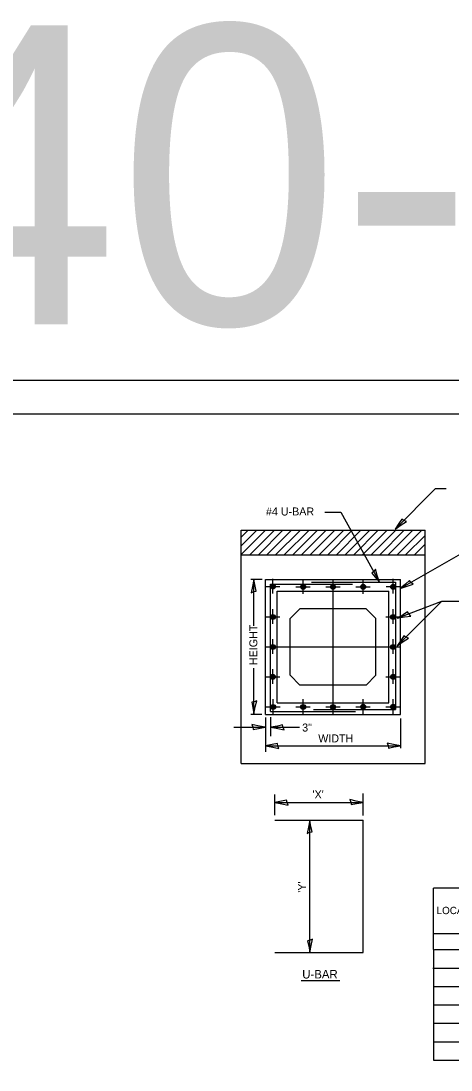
# Model space of a CAD drawing. Extents: x 2133490 to 2172050, y 2138301 to 2145980.
# Drawn here: x 2145603 to 2145925, y 2145157 to 2145944 of the extents above; entities that cross this region are included whole.
import ezdxf

# ---------------------------------------------------------------- set-up
doc = ezdxf.new("R2010")
doc.units = 0
for name, color, linetype in [('Level 23', 7, 'Continuous'), ('Level 40', 7, 'Continuous'), ('Level 63', 7, 'Continuous'), ('ROW_PR_Notes', 7, 'Continuous'), ('Sheets_50 Reference Boundary', 7, 'Continuous'), ('Sheets_General Details', 7, 'Continuous'), ('Sheets_Printer Plotting Border', 7, 'Continuous')]:
    doc.layers.add(name, color=color, linetype=linetype)

msp = doc.modelspace()

# ---------------------------------------------------------------- linework, layer by layer
at = {"layer": 'Level 23'}
for p, q in [((2145912.22, 2145247.63), (2145912.22, 2145293.63)), ((2146044.7, 2145293.63), (2145912.22, 2145293.63)), ((2146044.7, 2145259.59), (2145912.56, 2145259.59)), ((2145912.22, 2145247.63), (2145912.22, 2145164.83)), ((2145912.99, 2145247.63), (2146044.7, 2145247.63)), ((2145911.69, 2145233.83), (2146044.7, 2145233.83)), ((2145912.99, 2145220.03), (2146044.7, 2145220.03)), ((2145912.56, 2145206.23), (2146044.7, 2145206.23)), ((2145912.13, 2145192.43), (2146044.7, 2145192.43)), ((2145912.56, 2145178.63), (2146044.7, 2145178.63)), ((2145912.22, 2145164.83), (2146044.7, 2145164.83))]:
    msp.add_line(p, q, dxfattribs=at)
at = {"layer": 'Level 40'}
for p, q in [((2145836.76, 2145427.74), (2145836.76, 2145517.16)), ((2145786.51, 2145474.63), (2145882.02, 2145474.63))]:
    msp.add_line(p, q, dxfattribs=at)
for centre, radius in [((2145791.72, 2145519.86), 1.84), ((2145791.72, 2145519.86), 1.52), ((2145791.72, 2145519.86), 1.23), ((2145791.72, 2145519.86), 0.774), ((2145814.31, 2145519.62), 1.84), ((2145814.31, 2145519.62), 1.52), ((2145814.31, 2145519.62), 1.23), ((2145836.76, 2145519.62), 1.84), ((2145836.76, 2145519.62), 1.52), ((2145836.76, 2145519.62), 1.23), ((2145859.34, 2145519.62), 1.84), ((2145859.34, 2145519.62), 1.52), ((2145859.34, 2145519.62), 1.23), ((2145881.89, 2145519.69), 1.84), ((2145881.89, 2145519.69), 1.52), ((2145881.89, 2145519.69), 1.23), ((2145791.72, 2145519.86), 0.373), ((2145814.31, 2145519.62), 0.774), ((2145814.31, 2145519.62), 0.373), ((2145836.76, 2145519.62), 0.774), ((2145836.76, 2145519.62), 0.373), ((2145859.34, 2145519.62), 0.774), ((2145859.34, 2145519.62), 0.373), ((2145881.89, 2145519.69), 0.774), ((2145881.89, 2145519.69), 0.373), ((2145791.58, 2145497.01), 1.84), ((2145791.58, 2145497.01), 1.52), ((2145791.58, 2145497.01), 1.23), ((2145791.58, 2145497.01), 0.774), ((2145791.58, 2145497.01), 0.373), ((2145881.79, 2145497.01), 1.84), ((2145881.79, 2145497.01), 1.52), ((2145881.79, 2145497.01), 1.23), ((2145881.79, 2145497.01), 0.774), ((2145881.79, 2145497.01), 0.373), ((2145791.58, 2145474.56), 1.84), ((2145791.58, 2145474.56), 1.52), ((2145791.58, 2145474.56), 1.23), ((2145791.58, 2145474.56), 0.774), ((2145791.58, 2145474.56), 0.373), ((2145881.79, 2145474.56), 1.84), ((2145881.79, 2145474.56), 1.52), ((2145881.79, 2145474.56), 1.23), ((2145881.79, 2145474.56), 0.774), ((2145881.79, 2145474.56), 0.373), ((2145791.58, 2145452.11), 1.84), ((2145791.58, 2145452.11), 1.52), ((2145791.58, 2145452.11), 1.23), ((2145791.58, 2145452.11), 0.774), ((2145791.58, 2145452.11), 0.373), ((2145881.79, 2145452.11), 1.84), ((2145881.79, 2145452.11), 1.52), ((2145881.79, 2145452.11), 1.23), ((2145881.79, 2145452.11), 0.774), ((2145881.79, 2145452.11), 0.373), ((2145791.86, 2145429.52), 1.84), ((2145791.86, 2145429.52), 1.52), ((2145791.86, 2145429.52), 1.23), ((2145791.86, 2145429.52), 0.774), ((2145791.86, 2145429.52), 0.373), ((2145814.31, 2145429.52), 1.84), ((2145814.31, 2145429.52), 1.52), ((2145814.31, 2145429.52), 1.23), ((2145814.31, 2145429.52), 0.774), ((2145814.31, 2145429.52), 0.373), ((2145836.76, 2145429.52), 1.84), ((2145836.76, 2145429.52), 1.52), ((2145836.76, 2145429.52), 1.23), ((2145836.76, 2145429.52), 0.774), ((2145836.76, 2145429.52), 0.373), ((2145859.34, 2145429.66), 1.84), ((2145859.34, 2145429.66), 1.52), ((2145859.34, 2145429.66), 1.23), ((2145859.34, 2145429.66), 0.774), ((2145859.34, 2145429.66), 0.373), ((2145881.79, 2145429.66), 1.84), ((2145881.79, 2145429.66), 1.52), ((2145881.79, 2145429.66), 1.23), ((2145881.79, 2145429.66), 0.774), ((2145881.79, 2145429.66), 0.373)]:
    msp.add_circle(centre, radius, dxfattribs=at)
at = {"layer": 'Level 63'}
for p, q in [((2145913.43, 2145593.11), (2145883.31, 2145563)), ((2145921.68, 2145593.11), (2145913.43, 2145593.11)), ((2145830.6, 2145575.64), (2145842.65, 2145575.64)), ((2145842.65, 2145575.64), (2145871.61, 2145523.03)), ((2145918.46, 2145508.95), (2145884.86, 2145475.52)), ((2145885, 2145496.17), (2145918.46, 2145508.95)), ((2145918.46, 2145508.95), (2145931.8, 2145508.95)), ((2145789.84, 2145421.95), (2145789.84, 2145407.72)), ((2145762.3, 2145414.41), (2145785.76, 2145414.41)), ((2145790.08, 2145414.41), (2145811.51, 2145414.41))]:
    msp.add_line(p, q, dxfattribs=at)
for points in [[(2145891.86, 2145568.59), (2145889.93, 2145569.37), (2145888.4, 2145570.45), (2145886.24, 2145567.14), (2145883.31, 2145563), (2145887.77, 2145566.08)], [(2145868.62, 2145532.79), (2145867.33, 2145531.15), (2145865.87, 2145529.99), (2145868.44, 2145526.99), (2145871.61, 2145523.03), (2145869.89, 2145528.17)], [(2145775.33, 2145515.23), (2145777.25, 2145516.04), (2145779.09, 2145516.36), (2145778.29, 2145520.23), (2145777.42, 2145525.23), (2145776.45, 2145519.89)], [(2145896.91, 2145521.6), (2145895.25, 2145522.86), (2145894.06, 2145524.3), (2145891.11, 2145521.68), (2145887.2, 2145518.44), (2145892.31, 2145520.25)], [(2145895.09, 2145497.78), (2145893.64, 2145499.29), (2145892.69, 2145500.89), (2145889.36, 2145498.76), (2145885, 2145496.17), (2145890.33, 2145497.16)], [(2145893.43, 2145481.09), (2145891.49, 2145481.87), (2145889.97, 2145482.96), (2145887.8, 2145479.66), (2145884.86, 2145475.52), (2145889.33, 2145478.59)], [(2145779.51, 2145434.27), (2145777.59, 2145433.46), (2145775.75, 2145433.14), (2145776.56, 2145429.27), (2145777.42, 2145424.27), (2145778.39, 2145429.61)], [(2145775.76, 2145416.51), (2145776.57, 2145414.58), (2145776.89, 2145412.74), (2145780.76, 2145413.55), (2145785.76, 2145414.41), (2145780.42, 2145415.38)], [(2145800.08, 2145412.32), (2145799.27, 2145414.24), (2145798.95, 2145416.09), (2145795.08, 2145415.28), (2145790.08, 2145414.41), (2145795.42, 2145413.44)], [(2145796.24, 2145398.37), (2145795.43, 2145400.29), (2145795.11, 2145402.13), (2145791.24, 2145401.33), (2145786.24, 2145400.46), (2145791.58, 2145399.49)], [(2145877.37, 2145402.55), (2145878.18, 2145400.63), (2145878.5, 2145398.79), (2145882.37, 2145399.6), (2145887.37, 2145400.46), (2145882.03, 2145401.43)], [(2145803.1, 2145355.96), (2145802.28, 2145357.88), (2145801.97, 2145359.72), (2145798.1, 2145358.91), (2145793.1, 2145358.05), (2145798.43, 2145357.08)], [(2145849.34, 2145360.14), (2145850.16, 2145358.22), (2145850.47, 2145356.38), (2145854.34, 2145357.18), (2145859.34, 2145358.05), (2145854.01, 2145359.02)], [(2145817.29, 2145334.82), (2145819.21, 2145335.64), (2145821.06, 2145335.95), (2145820.25, 2145339.82), (2145819.38, 2145344.82), (2145818.41, 2145339.49)], [(2145821.48, 2145255.46), (2145819.55, 2145254.65), (2145817.71, 2145254.33), (2145818.52, 2145250.46), (2145819.38, 2145245.46), (2145820.35, 2145250.8)]]:
    msp.add_lwpolyline(points, close=True, dxfattribs=at)
at = {"layer": 'ROW_PR_Notes'}
for p, q in [((2145767.76, 2145387.23), (2145767.76, 2145562.03)), ((2145767.76, 2145562.03), (2145905.76, 2145562.03)), ((2145767.82, 2145550.27), (2145779.62, 2145562.07)), ((2145767.88, 2145556.83), (2145773.19, 2145562.14)), ((2145767.89, 2145543.83), (2145786.19, 2145562.13)), ((2145774.32, 2145543.76), (2145792.53, 2145561.97)), ((2145780.8, 2145543.73), (2145799.09, 2145562.03)), ((2145787.19, 2145543.61), (2145805.74, 2145562.17)), ((2145793.67, 2145543.59), (2145812.09, 2145562.01)), ((2145800.4, 2145543.82), (2145818.52, 2145561.94)), ((2145806.7, 2145543.61), (2145825.17, 2145562.08)), ((2145813.22, 2145543.63), (2145831.74, 2145562.14)), ((2145819.87, 2145543.77), (2145838.21, 2145562.11)), ((2145826.31, 2145543.7), (2145844.51, 2145561.91)), ((2145832.78, 2145543.67), (2145851.25, 2145562.14)), ((2145839.35, 2145543.73), (2145857.68, 2145562.07)), ((2145845.82, 2145543.7), (2145864.12, 2145561.99)), ((2145852.26, 2145543.63), (2145870.68, 2145562.05)), ((2145858.77, 2145543.64), (2145877.11, 2145561.98)), ((2145865.34, 2145543.7), (2145883.63, 2145561.99)), ((2145871.86, 2145543.71), (2145890.24, 2145562.09)), ((2145878.42, 2145543.77), (2145896.5, 2145561.85)), ((2145884.76, 2145543.61), (2145903.06, 2145561.9)), ((2145905.76, 2145387.23), (2145905.76, 2145562.03)), ((2145887.2, 2145518.44), (2145949.51, 2145554.19)), ((2145891.24, 2145543.58), (2145905.83, 2145558.17)), ((2145897.85, 2145543.68), (2145905.86, 2145551.7)), ((2145767.76, 2145543.63), (2145905.76, 2145543.63)), ((2145783.73, 2145525.23), (2145775.19, 2145525.23)), ((2145777.42, 2145490.52), (2145777.42, 2145525.23)), ((2145786.16, 2145424.03), (2145786.16, 2145525.23)), ((2145786.16, 2145525.23), (2145887.36, 2145525.23)), ((2145789.84, 2145426.19), (2145789.84, 2145521.55)), ((2145789.84, 2145521.55), (2145851.45, 2145521.55)), ((2145791.72, 2145519.86), (2145791.72, 2145525.72)), ((2145814.31, 2145519.62), (2145814.31, 2145525.48)), ((2145820.75, 2145523.17), (2145883.68, 2145523.17)), ((2145836.76, 2145519.62), (2145836.76, 2145525.48)), ((2145859.34, 2145519.62), (2145859.34, 2145525.48)), ((2145881.89, 2145519.69), (2145881.89, 2145525.55)), ((2145883.68, 2145523.17), (2145883.68, 2145427.71)), ((2145887.36, 2145424.03), (2145887.36, 2145525.23)), ((2145786.38, 2145519.97), (2145796.98, 2145519.97)), ((2145791.72, 2145514.7), (2145791.72, 2145519.86)), ((2145794.9, 2145516.49), (2145878.62, 2145516.49)), ((2145794.9, 2145432.77), (2145794.9, 2145516.49)), ((2145808.97, 2145519.72), (2145819.58, 2145519.72)), ((2145814.31, 2145514.46), (2145814.31, 2145519.62)), ((2145814.31, 2145514.46), (2145814.31, 2145519.62)), ((2145814.31, 2145514.46), (2145814.31, 2145519.62)), ((2145814.31, 2145514.46), (2145814.31, 2145519.62)), ((2145831.42, 2145519.72), (2145842.03, 2145519.72)), ((2145836.76, 2145514.46), (2145836.76, 2145519.62)), ((2145836.76, 2145514.46), (2145836.76, 2145519.62)), ((2145836.76, 2145514.46), (2145836.76, 2145519.62)), ((2145854, 2145519.72), (2145864.61, 2145519.72)), ((2145859.34, 2145514.46), (2145859.34, 2145519.62)), ((2145859.34, 2145514.46), (2145859.34, 2145519.62)), ((2145876.55, 2145519.79), (2145887.16, 2145519.79)), ((2145878.62, 2145432.77), (2145878.62, 2145516.49)), ((2145881.89, 2145514.53), (2145881.89, 2145519.69)), ((2145786.24, 2145497.12), (2145796.85, 2145497.12)), ((2145786.24, 2145497.12), (2145796.85, 2145497.12)), ((2145791.58, 2145497.01), (2145791.58, 2145502.87)), ((2145791.58, 2145491.85), (2145791.58, 2145497.01)), ((2145811.92, 2145503.23), (2145804.56, 2145495.87)), ((2145861.6, 2145503.23), (2145811.92, 2145503.23)), ((2145868.96, 2145495.87), (2145861.6, 2145503.23)), ((2145876.45, 2145497.12), (2145887.06, 2145497.12)), ((2145876.45, 2145497.12), (2145887.06, 2145497.12)), ((2145881.79, 2145497.01), (2145881.79, 2145502.87)), ((2145881.79, 2145491.85), (2145881.79, 2145497.01)), ((2145804.56, 2145453.38), (2145804.56, 2145495.87)), ((2145868.96, 2145453.38), (2145868.96, 2145495.87)), ((2145786.24, 2145474.66), (2145796.85, 2145474.66)), ((2145786.24, 2145474.66), (2145796.85, 2145474.66)), ((2145786.24, 2145474.66), (2145796.85, 2145474.66)), ((2145791.58, 2145474.56), (2145791.58, 2145480.42)), ((2145791.58, 2145469.4), (2145791.58, 2145474.56)), ((2145876.45, 2145474.66), (2145887.06, 2145474.66)), ((2145876.45, 2145474.66), (2145887.06, 2145474.66)), ((2145876.45, 2145474.66), (2145887.06, 2145474.66)), ((2145881.79, 2145474.56), (2145881.79, 2145480.42)), ((2145881.79, 2145469.4), (2145881.79, 2145474.56)), ((2145777.42, 2145424.27), (2145777.42, 2145458.62)), ((2145791.58, 2145452.11), (2145791.58, 2145457.97)), ((2145881.79, 2145452.11), (2145881.79, 2145457.97)), ((2145786.24, 2145452.21), (2145796.85, 2145452.21)), ((2145786.24, 2145452.21), (2145796.85, 2145452.21)), ((2145791.58, 2145446.95), (2145791.58, 2145452.11)), ((2145804.56, 2145453.38), (2145811.92, 2145446.02)), ((2145861.6, 2145446.02), (2145868.96, 2145453.38)), ((2145876.45, 2145452.21), (2145887.06, 2145452.21)), ((2145876.45, 2145452.21), (2145887.06, 2145452.21)), ((2145881.79, 2145446.95), (2145881.79, 2145452.11)), ((2145861.6, 2145446.02), (2145811.92, 2145446.02)), ((2145883.75, 2145444.27), (2145883.68, 2145444.27)), ((2145791.86, 2145429.52), (2145791.86, 2145435.38)), ((2145814.31, 2145429.52), (2145814.31, 2145435.38)), ((2145836.76, 2145429.52), (2145836.76, 2145435.38)), ((2145836.76, 2145429.52), (2145836.76, 2145435.38)), ((2145859.34, 2145429.66), (2145859.34, 2145435.52)), ((2145859.34, 2145429.66), (2145859.34, 2145435.52)), ((2145881.79, 2145429.66), (2145881.79, 2145435.52)), ((2145786.52, 2145429.62), (2145797.13, 2145429.62)), ((2145791.86, 2145424.36), (2145791.86, 2145429.52)), ((2145794.9, 2145432.77), (2145878.62, 2145432.77)), ((2145808.97, 2145429.62), (2145819.58, 2145429.62)), ((2145814.31, 2145424.36), (2145814.31, 2145429.52)), ((2145822.14, 2145427.71), (2145883.68, 2145427.71)), ((2145831.42, 2145429.62), (2145842.03, 2145429.62)), ((2145836.76, 2145424.36), (2145836.76, 2145429.52)), ((2145854, 2145429.76), (2145864.61, 2145429.76)), ((2145859.34, 2145424.5), (2145859.34, 2145429.66)), ((2145876.45, 2145429.76), (2145887.06, 2145429.76)), ((2145881.79, 2145424.5), (2145881.79, 2145429.66)), ((2145783.45, 2145424.03), (2145775.01, 2145424.03)), ((2145786.16, 2145424.03), (2145887.36, 2145424.03)), ((2145786.16, 2145421.67), (2145786.16, 2145396)), ((2145789.84, 2145426.19), (2145853.54, 2145426.19)), ((2145887.36, 2145420.83), (2145887.36, 2145398.75)), ((2145786.24, 2145400.46), (2145887.37, 2145400.46)), ((2145767.76, 2145387.23), (2145905.76, 2145387.23)), ((2145793.1, 2145348.36), (2145793.1, 2145364.08)), ((2145859.34, 2145348.2), (2145859.34, 2145364.75)), ((2145793.1, 2145358.05), (2145859.34, 2145358.05)), ((2145793.1, 2145344.82), (2145859.34, 2145344.82)), ((2145819.38, 2145245.46), (2145819.38, 2145344.82)), ((2145859.34, 2145245.46), (2145859.34, 2145344.82)), ((2145793.1, 2145245.46), (2145859.34, 2145245.46)), ((2145812.86, 2145224.49), (2145841.79, 2145224.49))]:
    msp.add_line(p, q, dxfattribs=at)
at = {"layer": 'Sheets_50 Reference Boundary'}
msp.add_lwpolyline([(2144950.12, 2145649.45), (2146525.12, 2145649.45), (2146525.12, 2144649.46), (2144950.12, 2144649.46)], close=True, dxfattribs=at)
at = {"layer": 'Sheets_General Details'}
msp.add_line((2146550.12, 2145674.46), (2144850.12, 2145674.46), dxfattribs=at)
msp.add_lwpolyline([(2144950.12, 2145649.46), (2146525.12, 2145649.46), (2146525.12, 2144599.46), (2144950.12, 2144599.46)], close=True, dxfattribs=at)
at = {"layer": 'Sheets_Printer Plotting Border'}
msp.add_lwpolyline([(2144850.12, 2144574.46), (2146550.12, 2144574.46), (2146550.12, 2145674.46), (2144850.12, 2145674.46)], close=True, dxfattribs=at)

# ---------------------------------------------------------------- texts
at = {"layer": 'Level 23'}
msp.add_text('LOCATION', height=5.5, dxfattribs=at).set_placement((2145914.51, 2145274.27))
at = {"layer": 'Level 63'}
for s, p in [('#4 U-BAR', (2145786.47, 2145573.14)), ('3"', (2145813.64, 2145411.16))]:
    msp.add_text(s, height=6, dxfattribs=at).set_placement(p)
at = {"layer": 'ROW_PR_Notes'}
for s, p in [('HEIGHT', (2145780.01, 2145460.98)), ("'Y'", (2145816.38, 2145290.32))]:
    msp.add_text(s, height=6, rotation=90, dxfattribs=at).set_placement(p)
for s, height, p in [('WIDTH', 6, (2145825.69, 2145403.03)), ("'X'", 6, (2145821.4, 2145361.05)), ('U-BAR', 6.4, (2145813.67, 2145226.02))]:
    msp.add_text(s, height=height, dxfattribs=at).set_placement(p)
at = {"layer": 'Sheets_General Details'}
msp.add_text('540-5', height=224, dxfattribs=at).set_placement((2145342.32, 2145716.54))

doc.saveas('drawing.dxf')
